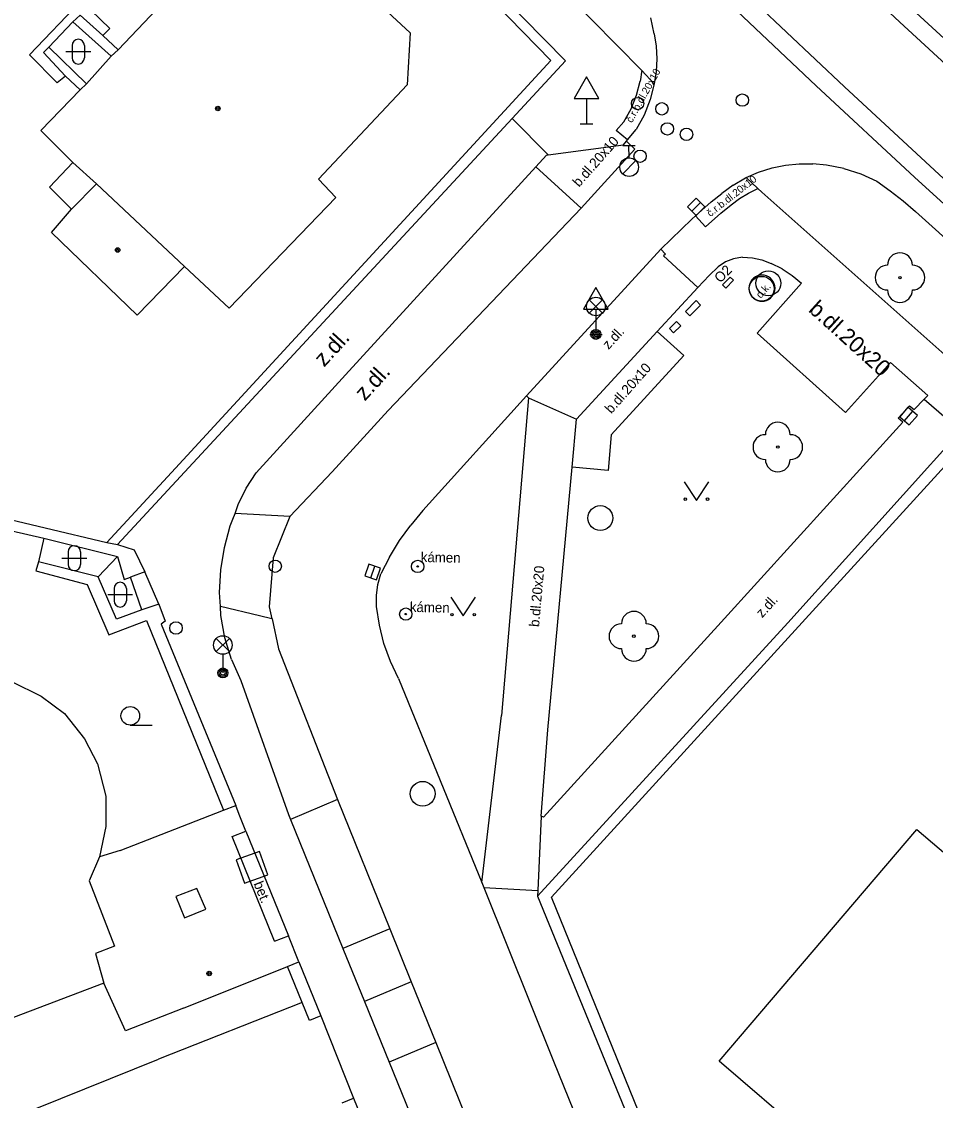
# Model space of a CAD drawing. Extents: x -600391 to -599491, y -1160176 to -1159402.
# Drawn here: x -599874.22 to -599837.4, y -1159988.38 to -1159944.9 of the extents above; entities that cross this region are included whole.
import ezdxf

# ---------------------------------------------------------------- set-up
doc = ezdxf.new("R2010")
doc.units = 0
for name, color, linetype in [('Level 10', 7, 'Continuous'), ('Level 11', 7, 'Continuous'), ('Level 13', 7, 'Continuous'), ('Level 22', 7, 'Continuous'), ('Level 24', 7, 'Continuous'), ('Level 25', 7, 'Continuous'), ('Level 26', 7, 'Continuous'), ('Level 27', 7, 'Continuous'), ('Level 28', 7, 'Continuous'), ('Level 33', 7, 'Continuous'), ('Level 34', 7, 'Continuous'), ('Level 36', 7, 'Continuous'), ('Level 39', 7, 'Continuous'), ('Level 40', 7, 'Continuous'), ('Level 41', 7, 'Continuous'), ('Level 42', 7, 'Continuous'), ('Level 5', 7, 'Continuous'), ('Level 7', 7, 'Continuous'), ('Level 8', 7, 'Continuous')]:
    doc.layers.add(name, color=color, linetype=linetype)

msp = doc.modelspace()

# ---------------------------------------------------------------- linework, layer by layer
at = {"layer": 'Level 10'}
for points in [[(-599848.73, -1159945.4), (-599848.87, -1159944.75)], [(-599848.73, -1159945.4), (-599848.65, -1159945.9), (-599848.62, -1159946.41), (-599848.65, -1159946.91), (-599848.73, -1159947.41)], [(-599848.73, -1159947.41), (-599848.89, -1159948.05), (-599849.14, -1159948.67), (-599849.46, -1159949.25)], [(-599849.97, -1159949.87), (-599849.85, -1159949.73), (-599849.81, -1159949.67), (-599849.46, -1159949.25)], [(-599853.07, -1159950.29), (-599853, -1159950.28), (-599849.97, -1159949.87)], [(-599853.07, -1159950.29), (-599853.5, -1159950.76)], [(-599853.5, -1159950.76), (-599861.17, -1159959.14)], [(-599845.55, -1159951.49), (-599845.05, -1159951.2), (-599845.02, -1159951.19), (-599844.53, -1159950.97), (-599843.98, -1159950.8)], [(-599843.98, -1159950.8), (-599843.44, -1159950.69), (-599842.89, -1159950.64), (-599842.34, -1159950.64)], [(-599841.79, -1159950.69), (-599842.34, -1159950.64)], [(-599841.09, -1159950.82), (-599841.79, -1159950.69)], [(-599841.09, -1159950.82), (-599841.79, -1159950.69)], [(-599841.09, -1159950.82), (-599840.41, -1159951.04), (-599839.76, -1159951.34)], [(-599845.55, -1159951.49), (-599846.01, -1159951.83)], [(-599839.76, -1159951.34), (-599839.22, -1159951.72), (-599838.7, -1159952.13), (-599838.2, -1159952.56)], [(-599847.21, -1159952.86), (-599847.07, -1159952.73), (-599846.44, -1159952.17), (-599846.01, -1159951.83)], [(-599838.2, -1159952.56), (-599832.65, -1159957.56), (-599829.31, -1159960.54), (-599827.38, -1159961.84)], [(-599847.21, -1159952.86), (-599848.47, -1159954.08)], [(-599858.05, -1159964.6), (-599853.87, -1159959.98), (-599848.47, -1159954.08)], [(-599861.17, -1159959.14), (-599864.77, -1159963.09)], [(-599865.17, -1159963.71), (-599864.77, -1159963.09)], [(-599865.49, -1159964.37), (-599865.17, -1159963.71)], [(-599865.71, -1159964.95), (-599865.62, -1159964.72), (-599865.49, -1159964.37)], [(-599858.05, -1159964.6), (-599858.54, -1159965.19)], [(-599866.25, -1159967.91), (-599866.19, -1159967), (-599866.04, -1159966.1), (-599865.81, -1159965.22), (-599865.71, -1159964.95)], [(-599859.39, -1159966.48), (-599858.99, -1159965.82), (-599858.54, -1159965.19)], [(-599859.39, -1159966.48), (-599859.75, -1159967.16)], [(-599859.92, -1159968.47), (-599859.92, -1159968.03), (-599859.86, -1159967.59), (-599859.75, -1159967.16)], [(-599865.76, -1159970.61), (-599866.03, -1159969.73), (-599866.19, -1159968.83), (-599866.21, -1159968.48), (-599866.25, -1159967.91)], [(-599859.04, -1159971.38), (-599859.36, -1159970.69), (-599859.62, -1159969.97), (-599859.8, -1159969.23), (-599859.92, -1159968.47)], [(-599865.76, -1159970.61), (-599865.39, -1159971.45)], [(-599865.39, -1159971.45), (-599863.47, -1159976.85), (-599863.38, -1159977.06)], [(-599859.04, -1159971.38), (-599855.68, -1159979.6), (-599855.6, -1159979.79), (-599852.79, -1159986.79), (-599837.18, -1160025.28)], [(-599863.38, -1159977.06), (-599861.27, -1159982.25)], [(-599861.27, -1159982.25), (-599860.4, -1159984.39)], [(-599860.4, -1159984.39), (-599859.41, -1159986.83)], [(-599859.41, -1159986.83), (-599858.24, -1159989.71), (-599854.22, -1159999.63)]]:
    msp.add_lwpolyline(points, dxfattribs=at)
at = {"layer": 'Level 11'}
for points in [[(-599850.29, -1159932.9), (-599846.51, -1159936.62), (-599842.69, -1159940.3), (-599838.83, -1159943.93), (-599834.93, -1159947.53)], [(-599858.52, -1159933.61), (-599860.17, -1159935.25), (-599860.43, -1159935.51), (-599860.36, -1159935.58), (-599854.27, -1159941.76), (-599849.23, -1159946.88), (-599848.73, -1159947.41)], [(-599838.24, -1159951.17), (-599842.21, -1159947.5), (-599846.13, -1159943.78), (-599850, -1159940.01), (-599853.83, -1159936.2)], [(-599872.45, -1159947.1), (-599872.78, -1159947.37), (-599873.9, -1159946.24), (-599871.82, -1159944.07), (-599870.67, -1159945.19), (-599870.94, -1159945.46)], [(-599870.94, -1159945.46), (-599871.86, -1159944.65), (-599872.15, -1159944.91)], [(-599872.15, -1159944.91), (-599873.12, -1159945.93)], [(-599872.15, -1159944.91), (-599870.61, -1159946.3)], [(-599870.94, -1159945.46), (-599870.33, -1159946.05)], [(-599873.12, -1159945.93), (-599873.34, -1159946.15), (-599872.45, -1159947.1)], [(-599871.6, -1159947.41), (-599873.12, -1159945.93)], [(-599849.23, -1159946.88), (-599849.25, -1159947.02), (-599849.27, -1159947.16), (-599849.3, -1159947.3)], [(-599871.86, -1159947.65), (-599872.45, -1159947.1)], [(-599849.95, -1159948.94), (-599849.66, -1159948.42), (-599849.45, -1159947.87), (-599849.3, -1159947.3)], [(-599854.45, -1159948.81), (-599853, -1159950.28)], [(-599850.26, -1159949.3), (-599849.95, -1159948.94)], [(-599849.81, -1159949.67), (-599850.26, -1159949.3)], [(-599849.85, -1159949.73), (-599849.51, -1159950.05), (-599851.68, -1159952.42)], [(-599872.21, -1159952.46), (-599873.09, -1159951.58), (-599872.16, -1159950.58)], [(-599853.5, -1159950.76), (-599851.68, -1159952.42)], [(-599829.47, -1159965.01), (-599836.54, -1159958.76), (-599844.39, -1159951.78), (-599844.55, -1159951.63), (-599845.02, -1159951.19)], [(-599838.24, -1159951.17), (-599834.23, -1159954.83), (-599830.17, -1159958.45), (-599826.08, -1159962.02)], [(-599845.63, -1159952.29), (-599845.29, -1159952.04), (-599844.93, -1159951.82), (-599844.55, -1159951.63)], [(-599859.45, -1159960.57), (-599851.68, -1159952.42)], [(-599846.67, -1159953.18), (-599846.05, -1159952.63), (-599845.63, -1159952.29)], [(-599847.07, -1159952.73), (-599846.67, -1159953.18)], [(-599848.47, -1159954.08), (-599848.28, -1159954.27), (-599848.36, -1159954.35)], [(-599846.97, -1159955.62), (-599848.36, -1159954.35)], [(-599846.16, -1159954.79), (-599846.52, -1159955.14), (-599846.97, -1159955.62), (-599848.61, -1159957.39)], [(-599845.86, -1159954.59), (-599846.16, -1159954.79)], [(-599845.53, -1159954.46), (-599845.86, -1159954.59)], [(-599845.17, -1159954.4), (-599845.53, -1159954.46)], [(-599845.17, -1159954.4), (-599844.77, -1159954.42), (-599844.39, -1159954.5), (-599844.02, -1159954.65)], [(-599843.58, -1159954.87), (-599844.02, -1159954.65)], [(-599843.861, -1159955.646), (-599843.87, -1159955.554), (-599843.893, -1159955.466), (-599843.932, -1159955.383), (-599843.985, -1159955.308), (-599844.049, -1159955.243), (-599844.125, -1159955.19), (-599844.208, -1159955.151), (-599844.296, -1159955.128), (-599844.388, -1159955.12), (-599844.479, -1159955.128), (-599844.568, -1159955.151), (-599844.651, -1159955.19), (-599844.726, -1159955.243), (-599844.791, -1159955.308), (-599844.843, -1159955.383), (-599844.882, -1159955.466), (-599844.906, -1159955.554), (-599844.914, -1159955.646), (-599844.906, -1159955.737), (-599844.882, -1159955.826), (-599844.843, -1159955.909), (-599844.791, -1159955.984), (-599844.726, -1159956.049), (-599844.651, -1159956.102), (-599844.568, -1159956.14), (-599844.479, -1159956.164), (-599844.388, -1159956.172), (-599844.296, -1159956.164), (-599844.208, -1159956.14), (-599844.125, -1159956.102), (-599844.049, -1159956.049), (-599843.985, -1159955.984), (-599843.932, -1159955.909), (-599843.893, -1159955.826), (-599843.87, -1159955.737), (-599843.861, -1159955.646)], [(-599843.58, -1159954.87), (-599843.17, -1159955.14), (-599842.79, -1159955.45)], [(-599839.21, -1159958.64), (-599841.02, -1159960.66), (-599844.58, -1159957.46), (-599842.79, -1159955.45)], [(-599848.61, -1159957.39), (-599847.54, -1159958.36), (-599850.46, -1159961.55), (-599850.59, -1159963), (-599852.04, -1159962.86)], [(-599852.04, -1159962.86), (-599851.86, -1159960.92), (-599848.61, -1159957.39)], [(-599839.21, -1159958.64), (-599837.7, -1159959.97), (-599837.85, -1159960.12), (-599838.26, -1159960.53)], [(-599853.87, -1159959.98), (-599853.79, -1159960.07)], [(-599853.79, -1159960.07), (-599854.89, -1159972.86)], [(-599853.79, -1159960.07), (-599851.86, -1159960.92)], [(-599838.71, -1159961.04), (-599838.9, -1159960.89), (-599838.45, -1159960.39), (-599838.26, -1159960.53)], [(-599837.85, -1159960.12), (-599836.38, -1159961.39)], [(-599859.45, -1159960.57), (-599861.71, -1159963.05)], [(-599838.71, -1159961.04), (-599846.03, -1159969.11), (-599853.19, -1159976.96), (-599853.29, -1159976.92), (-599853.01, -1159973.44), (-599852.04, -1159962.86)], [(-599861.71, -1159963.05), (-599863.41, -1159964.85)], [(-599863.41, -1159964.85), (-599865.62, -1159964.72)], [(-599863.41, -1159964.85), (-599864.087, -1159966.508), (-599864.24, -1159968.486), (-599864.135, -1159968.971)], [(-599873.32, -1159965.72), (-599873.54, -1159966.67)], [(-599870.35, -1159966.46), (-599871.13, -1159967.28)], [(-599869.38, -1159968.61), (-599869.83, -1159967.29)], [(-599864.135, -1159968.971), (-599864.635, -1159968.852), (-599866.21, -1159968.48)], [(-599864.13, -1159968.97), (-599863.873, -1159970.179), (-599861.493, -1159976.249)], [(-599855.68, -1159979.6), (-599854.89, -1159972.86)], [(-599861.493, -1159976.249), (-599863.38, -1159977.06)], [(-599861.493, -1159976.249), (-599859.383, -1159981.465)], [(-599853.29, -1159976.92), (-599853.42, -1159979.92), (-599853.43, -1159980.14)], [(-599870.25, -1159978.31), (-599871.08, -1159978.56)], [(-599867.65, -1159981.02), (-599866.8, -1159980.67), (-599867.16, -1159979.83), (-599868.01, -1159980.16), (-599867.65, -1159981.02)], [(-599855.6, -1159979.79), (-599853.42, -1159979.92)], [(-599859.383, -1159981.465), (-599861.27, -1159982.25)], [(-599859.383, -1159981.465), (-599858.52, -1159983.602)], [(-599867.69, -1159984.66), (-599870.03, -1159985.57), (-599870.9, -1159983.65)], [(-599858.52, -1159983.602), (-599860.4, -1159984.39)], [(-599858.52, -1159983.602), (-599857.534, -1159986.045)], [(-599857.534, -1159986.045), (-599859.41, -1159986.83)], [(-599857.534, -1159986.045), (-599856.272, -1159989.17)]]:
    msp.add_lwpolyline(points, dxfattribs=at)
at = {"layer": 'Level 13'}
for points in [[(-599829.34, -1159953.56), (-599834.12, -1159949.27), (-599838.84, -1159944.93), (-599843.52, -1159940.54)], [(-599831.57, -1159956.21), (-599836.35, -1159951.9), (-599841.07, -1159947.53), (-599845.74, -1159943.11)]]:
    msp.add_lwpolyline(points, dxfattribs=at)
at = {"layer": 'Level 22'}
for centre in [(-599838.83, -1159955.22), (-599843.75, -1159962.05), (-599849.55, -1159969.67)]:
    msp.add_circle(centre, 0.05, dxfattribs=at)
for centre, start, end in [((-599838.83, -1159954.72), 0, 180), ((-599839.33, -1159955.22), 90, 270), ((-599838.33, -1159955.22), 270, 90), ((-599838.83, -1159955.72), 180, 0), ((-599843.75, -1159961.55), 0, 180), ((-599844.25, -1159962.05), 90, 270), ((-599843.25, -1159962.05), 270, 90), ((-599843.75, -1159962.55), 180, 0), ((-599849.55, -1159969.17), 0, 180), ((-599850.05, -1159969.67), 90, 270), ((-599849.05, -1159969.67), 270, 90), ((-599849.55, -1159970.17), 180, 0)]:
    msp.add_arc(centre, 0.5, start, end, dxfattribs=at)
at = {"layer": 'Level 24'}
for points in [[(-599845.98, -1159955.51), (-599845.67, -1159955.2)], [(-599845.67, -1159955.2), (-599845.54, -1159955.33)], [(-599845.85, -1159955.64), (-599845.98, -1159955.51)], [(-599845.54, -1159955.33), (-599845.85, -1159955.64)], [(-599847.47, -1159956.59), (-599847.04, -1159956.15)], [(-599846.86, -1159956.33), (-599847.29, -1159956.76)], [(-599847.04, -1159956.15), (-599846.86, -1159956.33)], [(-599847.29, -1159956.76), (-599847.47, -1159956.59)], [(-599848.12, -1159957.27), (-599847.83, -1159956.99)], [(-599847.95, -1159957.44), (-599848.12, -1159957.27)], [(-599847.66, -1159957.16), (-599847.95, -1159957.44)], [(-599847.83, -1159956.99), (-599847.66, -1159957.16)]]:
    msp.add_lwpolyline(points, dxfattribs=at)
at = {"layer": 'Level 25'}
for centre, radius in [((-599858.26, -1159966.86), 0.25), ((-599858.26, -1159966.86), 0.0303), ((-599858.74, -1159968.78), 0.25), ((-599858.74, -1159968.78), 0.0303)]:
    msp.add_circle(centre, radius, dxfattribs=at)
at = {"layer": 'Level 26'}
msp.add_lwpolyline([(-599865.242, -1159979.62), (-599864.3, -1159979.282), (-599864.638, -1159978.34), (-599865.58, -1159978.678)], close=True, dxfattribs=at)
at = {"layer": 'Level 27'}
for p, q in [((-599847.215, -1159952.548), (-599846.865, -1159952.192)), ((-599838.643, -1159960.989), (-599838.317, -1159960.611)), ((-599860.152, -1159967.316), (-599859.988, -1159966.844))]:
    msp.add_line(p, q, dxfattribs=at)
for points in [[(-599847.037, -1159952.724), (-599846.686, -1159952.367), (-599847.043, -1159952.016), (-599847.394, -1159952.373)], [(-599838.454, -1159961.153), (-599838.127, -1159960.774), (-599838.506, -1159960.447), (-599838.833, -1159960.826)], [(-599859.915, -1159967.398), (-599859.752, -1159966.925), (-599860.225, -1159966.762), (-599860.388, -1159967.235)]]:
    msp.add_lwpolyline(points, close=True, dxfattribs=at)
for centre in [(-599844.4, -1159955.67), (-599844.13, -1159955.45), (-599850.9, -1159964.91), (-599858.06, -1159976.02)]:
    msp.add_circle(centre, 0.5, dxfattribs=at)
at = {"layer": 'Level 28'}
for p, q in [((-599849.999, -1159949.898), (-599849.5, -1159949.892)), ((-599849.744, -1159950.395), (-599849.749, -1159949.895)), ((-599849.995, -1159951.045), (-599849.471, -1159950.509))]:
    msp.add_line(p, q, dxfattribs=at)
for centre, radius in [((-599845.18, -1159948.07), 0.25), ((-599849.4, -1159948.21), 0.25), ((-599848.42, -1159948.42), 0.25), ((-599848.2, -1159949.23), 0.25), ((-599847.43, -1159949.45), 0.25), ((-599849.74, -1159950.77), 0.375), ((-599849.3, -1159950.33), 0.25), ((-599864, -1159966.85), 0.25), ((-599868, -1159969.34), 0.25)]:
    msp.add_circle(centre, radius, dxfattribs=at)
at = {"layer": 'Level 33'}
for p, q in [((-599851.345, -1159956.65), (-599850.815, -1159956.12)), ((-599851.345, -1159956.12), (-599850.815, -1159956.65)), ((-599851.08, -1159956.76), (-599851.08, -1159957.51)), ((-599866.375, -1159970.29), (-599865.845, -1159969.76)), ((-599866.375, -1159969.76), (-599865.845, -1159970.29)), ((-599866.11, -1159970.4), (-599866.11, -1159971.15))]:
    msp.add_line(p, q, dxfattribs=at)
for centre, radius in [((-599851.08, -1159956.385), 0.375), ((-599851.08, -1159957.51), 0.2), ((-599851.08, -1159957.51), 0.145), ((-599851.08, -1159957.51), 0.0876), ((-599866.11, -1159970.025), 0.375), ((-599866.11, -1159971.15), 0.2), ((-599866.11, -1159971.15), 0.145), ((-599866.11, -1159971.15), 0.0876)]:
    msp.add_circle(centre, radius, dxfattribs=at)
at = {"layer": 'Level 34'}
for p, q in [((-599851.46, -1159948.002), (-599851.46, -1159949.02)), ((-599851.71, -1159949.02), (-599851.21, -1159949.02)), ((-599851.08, -1159956.492), (-599851.08, -1159957.51)), ((-599851.33, -1159957.51), (-599850.83, -1159957.51))]:
    msp.add_line(p, q, dxfattribs=at)
for points in [[(-599851.96, -1159948.002), (-599850.96, -1159948.002), (-599851.46, -1159947.136)], [(-599851.58, -1159956.492), (-599850.58, -1159956.492), (-599851.08, -1159955.626)]]:
    msp.add_lwpolyline(points, close=True, dxfattribs=at)
at = {"layer": 'Level 36'}
for p, q in [((-599872.436, -1159946.116), (-599871.436, -1159946.116)), ((-599872.186, -1159945.866), (-599872.186, -1159946.366)), ((-599871.686, -1159945.866), (-599871.686, -1159946.366)), ((-599872.596, -1159966.526), (-599871.596, -1159966.526)), ((-599872.346, -1159966.276), (-599872.346, -1159966.776)), ((-599871.846, -1159966.276), (-599871.846, -1159966.776)), ((-599870.496, -1159967.746), (-599870.496, -1159968.246)), ((-599869.996, -1159967.746), (-599869.996, -1159968.246)), ((-599870.746, -1159967.996), (-599869.746, -1159967.996)), ((-599869.84, -1159973.255), (-599868.965, -1159973.255))]:
    msp.add_line(p, q, dxfattribs=at)
for points in [[(-599847.53, -1159963.45), (-599847.03, -1159964.2), (-599846.53, -1159963.45)], [(-599856.93, -1159968.1), (-599856.43, -1159968.85), (-599855.93, -1159968.1)]]:
    msp.add_lwpolyline(points, dxfattribs=at)
for centre, radius in [((-599847.48, -1159964.15), 0.05), ((-599846.581, -1159964.15), 0.05), ((-599856.88, -1159968.8), 0.05), ((-599855.981, -1159968.8), 0.05), ((-599869.84, -1159972.88), 0.375)]:
    msp.add_circle(centre, radius, dxfattribs=at)
for centre, start, end in [((-599871.936, -1159945.866), 0, 180), ((-599871.936, -1159946.366), 180, 0), ((-599872.096, -1159966.276), 0, 180), ((-599872.096, -1159966.776), 180, 0), ((-599870.246, -1159967.746), 0, 180), ((-599870.246, -1159968.246), 180, 0)]:
    msp.add_arc(centre, 0.25, start, end, dxfattribs=at)
at = {"layer": 'Level 39'}
for centre, radius in [((-599866.31, -1159948.41), 0.09), ((-599866.31, -1159948.41), 0.0398), ((-599870.35, -1159954.11), 0.09), ((-599870.35, -1159954.11), 0.0398), ((-599866.66, -1159983.26), 0.09), ((-599866.66, -1159983.26), 0.0398)]:
    msp.add_circle(centre, radius, dxfattribs=at)
at = {"layer": 'Level 5'}
for points in [[(-599870.33, -1159946.05), (-599865.39, -1159940.83)], [(-599860.57, -1159943.49), (-599858.56, -1159945.36)], [(-599858.56, -1159945.36), (-599858.69, -1159947.46)], [(-599870.61, -1159946.3), (-599870.33, -1159946.05)], [(-599871.6, -1159947.41), (-599870.61, -1159946.3)], [(-599871.86, -1159947.65), (-599871.6, -1159947.41)], [(-599873.45, -1159949.3), (-599871.86, -1159947.65)], [(-599858.69, -1159947.46), (-599862.26, -1159951.25)], [(-599872.16, -1159950.58), (-599873.45, -1159949.3)], [(-599871.2, -1159951.44), (-599872.16, -1159950.58)], [(-599862.26, -1159951.25), (-599861.56, -1159951.99)], [(-599872.21, -1159952.46), (-599871.2, -1159951.44)], [(-599871.2, -1159951.44), (-599867.65, -1159954.78)], [(-599861.56, -1159951.99), (-599865.86, -1159956.45)], [(-599873.02, -1159953.4), (-599872.21, -1159952.46)], [(-599869.56, -1159956.73), (-599873.02, -1159953.4)], [(-599867.65, -1159954.78), (-599869.56, -1159956.73)], [(-599865.86, -1159956.45), (-599867.65, -1159954.78)], [(-599874.62, -1159971.5), (-599873.43, -1159972.09)], [(-599873.43, -1159972.09), (-599872.49, -1159972.79)], [(-599872.49, -1159972.79), (-599871.68, -1159973.81)], [(-599871.68, -1159973.81), (-599871.16, -1159974.81)], [(-599871.16, -1159974.81), (-599870.83, -1159976.12)], [(-599870.83, -1159976.12), (-599870.82, -1159977.34)], [(-599870.25, -1159978.31), (-599866.08, -1159976.68), (-599865.59, -1159976.49)], [(-599865.18, -1159977.52), (-599865.45, -1159976.85), (-599865.59, -1159976.49)], [(-599870.82, -1159977.34), (-599871.08, -1159978.56)], [(-599865.73, -1159977.74), (-599865.18, -1159977.52)], [(-599864.03, -1159981.96), (-599865.73, -1159977.74)], [(-599865.18, -1159977.52), (-599863.47, -1159981.74)], [(-599846.11, -1159986.79), (-599838.15, -1159977.46)], [(-599838.15, -1159977.46), (-599830.14, -1159984.27)], [(-599871.08, -1159978.56), (-599871.5, -1159979.53)], [(-599871.5, -1159979.53), (-599870.47, -1159982.16)], [(-599867.69, -1159984.66), (-599863.51, -1159982.98), (-599863.05, -1159982.79), (-599863.47, -1159981.74)], [(-599864.03, -1159981.96), (-599863.47, -1159981.74)], [(-599870.47, -1159982.16), (-599871.24, -1159982.46)], [(-599871.24, -1159982.46), (-599870.9, -1159983.65)], [(-599870.9, -1159983.65), (-599874.54, -1159985.04)], [(-599839.05, -1159992.87), (-599846.11, -1159986.79)]]:
    msp.add_lwpolyline(points, dxfattribs=at)
at = {"layer": 'Level 7'}
for points in [[(-599852.3, -1159946.48), (-599861.68, -1159936.95)], [(-599861.94, -1159937.2), (-599852.89, -1159946.47), (-599868.02, -1159962.9), (-599870.78, -1159965.89)], [(-599852.3, -1159946.48), (-599854.45, -1159948.81), (-599870.36, -1159965.98)], [(-599836.38, -1159961.39), (-599843.35, -1159969.13), (-599853.43, -1159980.14)], [(-599835.15, -1160023.79), (-599852.87, -1159980.19), (-599836.32, -1159962.05)], [(-599878.25, -1159964.12), (-599870.78, -1159965.89)], [(-599877.6, -1159967.16), (-599877.68, -1159964.72), (-599873.32, -1159965.72)], [(-599873.32, -1159965.72), (-599870.35, -1159966.46)], [(-599870.78, -1159965.89), (-599870.36, -1159965.98)], [(-599870.36, -1159965.98), (-599869.68, -1159966.19)], [(-599870.35, -1159966.46), (-599870.08, -1159967.39)], [(-599869.68, -1159966.19), (-599869.25, -1159967.07)], [(-599873.54, -1159966.67), (-599873.64, -1159967.04), (-599871.58, -1159967.59), (-599870.71, -1159969.62), (-599869.19, -1159969.04), (-599866.08, -1159976.68)], [(-599871.13, -1159967.28), (-599873.54, -1159966.67)], [(-599869.38, -1159968.61), (-599870.39, -1159968.99), (-599871.13, -1159967.28)], [(-599870.08, -1159967.39), (-599869.83, -1159967.29)], [(-599869.25, -1159967.07), (-599869.83, -1159967.29)], [(-599868.69, -1159968.38), (-599869.38, -1159968.61)], [(-599868.69, -1159968.38), (-599868.43, -1159969.07)], [(-599868.43, -1159969.07), (-599868.6, -1159969.18)], [(-599868.6, -1159969.18), (-599865.59, -1159976.49)], [(-599853.43, -1159980.14), (-599835.49, -1160023.94)], [(-599862.62, -1159985.16), (-599862.92, -1159984.43), (-599863.51, -1159982.98)], [(-599863.05, -1159982.79), (-599862.16, -1159984.97), (-599862.62, -1159985.16)], [(-599862.92, -1159984.43), (-599868.7, -1159986.71)], [(-599873.61, -1159988.69), (-599868.7, -1159986.71)], [(-599861.3, -1159988.47), (-599860.84, -1159988.28), (-599858.79, -1159993.32), (-599858.75, -1159993.42)]]:
    msp.add_lwpolyline(points, dxfattribs=at)
at = {"layer": 'Level 8'}
for points in [[(-599868.69, -1159968.38), (-599869.25, -1159967.07)], [(-599862.16, -1159984.97), (-599860.84, -1159988.28)]]:
    msp.add_lwpolyline(points, dxfattribs=at)

# ---------------------------------------------------------------- texts
at = {"layer": 'Level 40'}
for s, height, rotation, p in [('č.r.b.dl.20x10', 0.3, 61, (-599849.63, -1159949.01)), ('b.dl.20x10', 0.4, 48.5275, (-599851.76, -1159951.6)), ('č.r.b.dl.20x10', 0.3, 38, (-599846.47, -1159952.79)), ('d.k.', 0.3, 48.2896, (-599844.44, -1159956.08)), ('b.dl.20x20', 0.65, 317.8392, (-599842.55, -1159956.56)), ('z.dl.', 0.4, 47.3001, (-599850.57, -1159958.14)), ('z.dl.', 0.65, 47.4574, (-599862.03, -1159958.85)), ('b.dl.20x10', 0.4, 48.5275, (-599850.46, -1159960.73)), ('z.dl.', 0.65, 47.4574, (-599860.39, -1159960.22)), ('b.dl.20x20', 0.4, 85, (-599853.37, -1159969.31)), ('z.dl.', 0.4, 47.4299, (-599844.38, -1159968.95)), ('bet.', 0.4, 291.958, (-599864.88, -1159979.64))]:
    msp.add_text(s, height=height, rotation=rotation, dxfattribs=at).set_placement(p)
at = {"layer": 'Level 41'}
msp.add_text('O2', height=0.4, rotation=45, dxfattribs=at).set_placement((-599846.07, -1159955.46))
at = {"layer": 'Level 42'}
for p in [(-599858.14, -1159966.68), (-599858.58, -1159968.69)]:
    msp.add_text('kámen', height=0.4, rotation=358.9231, dxfattribs=at).set_placement(p)

doc.saveas('drawing.dxf')
